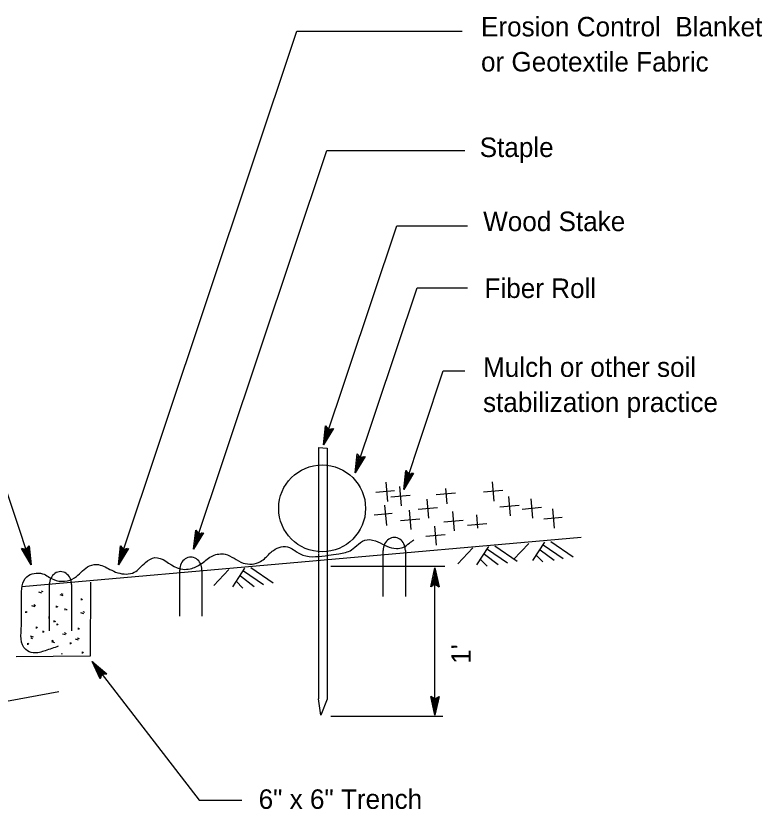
# Model space of a CAD drawing. Extents: x 6708945 to 6710368, y 1871409 to 1872338.
# Drawn here: x 6709230.9 to 6709460.4, y 1871973 to 1872217 of the extents above; entities that cross this region are included whole.
import ezdxf

# ---------------------------------------------------------------- set-up
doc = ezdxf.new("R2010")
doc.units = 0
for name, color, linetype in [('1 Control', 7, 'Continuous'), ('26 undefined', 7, 'Continuous'), ('57 Undefined', 7, 'Continuous'), ('60 Nongeo Data', 7, 'Continuous')]:
    doc.layers.add(name, color=color, linetype=linetype)

msp = doc.modelspace()

# ---------------------------------------------------------------- linework, layer by layer
at = {"layer": '1 Control'}
for p, q in [((6709343.86, 1872038.34), (6709343.86, 1872052.55)), ((6709350.7, 1872052.55), (6709350.7, 1872038.34)), ((6709281.29, 1872032.34), (6709281.29, 1872046.54)), ((6709288.12, 1872046.54), (6709288.12, 1872032.34)), ((6709241.22, 1872027.84), (6709241.22, 1872042.04)), ((6709248.06, 1872042.04), (6709248.06, 1872027.84))]:
    msp.add_line(p, q, dxfattribs=at)
for centre in [(6709347.28, 1872052.55), (6709284.7, 1872046.54), (6709244.64, 1872042.04)]:
    msp.add_ellipse(centre, major_axis=(0, 3.99), ratio=0.857645, start_param=4.712389, end_param=7.853982, dxfattribs=at)
at = {"layer": '26 undefined'}
for p, q in [((6709323.95, 1872084.22), (6709326.67, 1872084.01)), ((6709323.96, 1872084.2), (6709323.96, 1872078.02)), ((6709326.67, 1872084.01), (6709326.67, 1872078.12)), ((6709323.96, 1872078), (6709323.95, 1872051.85)), ((6709326.67, 1872078.09), (6709326.66, 1872051.6)), ((6709345.34, 1872067.65), (6709344.82, 1872073.54)), ((6709349.49, 1872066.27), (6709348.97, 1872072.21)), ((6709378, 1872067.73), (6709377.48, 1872073.67)), ((6709347.31, 1872070.84), (6709341.63, 1872070.33)), ((6709352.11, 1872069.5), (6709346.17, 1872068.97)), ((6709366.14, 1872070.17), (6709360.2, 1872069.64)), ((6709363.52, 1872066.94), (6709363.11, 1872071.63)), ((6709380.62, 1872070.96), (6709374.68, 1872070.43)), ((6709357.91, 1872062.44), (6709357.39, 1872068.37)), ((6709383.04, 1872063.2), (6709382.52, 1872069.14)), ((6709389.89, 1872062.51), (6709389.37, 1872068.44)), ((6709344.95, 1872060.25), (6709344.4, 1872066.49)), ((6709352.49, 1872058.99), (6709351.97, 1872064.92)), ((6709360.53, 1872065.66), (6709354.59, 1872065.14)), ((6709365.8, 1872058.56), (6709365.27, 1872064.49)), ((6709385.66, 1872066.43), (6709379.72, 1872065.9)), ((6709392.51, 1872065.73), (6709386.57, 1872065.2)), ((6709396.57, 1872059.44), (6709396.05, 1872065.37)), ((6709346.66, 1872063.87), (6709341.12, 1872063.38)), ((6709355.11, 1872062.21), (6709349.18, 1872061.69)), ((6709372.98, 1872059.36), (6709372.61, 1872063.49)), ((6709398.93, 1872062.64), (6709393.25, 1872062.14)), ((6709360.28, 1872054.14), (6709359.76, 1872060.07)), ((6709368.41, 1872061.78), (6709362.48, 1872061.26)), ((6709375.75, 1872060.78), (6709369.82, 1872060.26)), ((6709362.9, 1872057.36), (6709356.97, 1872056.84)), ((6709323.95, 1872051.63), (6709323.93, 1872006.88)), ((6709326.66, 1872051.67), (6709326.64, 1872006.83)), ((6709238.67, 1872040.16), (6709239.24, 1872039.88)), ((6709238.89, 1872039.43), (6709237.96, 1872039.7)), ((6709245.46, 1872038.63), (6709244.53, 1872038.9)), ((6709244.79, 1872039.36), (6709245.36, 1872039.09)), ((6709251.06, 1872037.25), (6709251.07, 1872037.73)), ((6709251.1, 1872037.7), (6709251.4, 1872037.5)), ((6709236.79, 1872035.21), (6709235.86, 1872035.48)), ((6709236.42, 1872035.94), (6709236.98, 1872035.66)), ((6709243.41, 1872035.01), (6709243.43, 1872035.5)), ((6709243.45, 1872035.46), (6709243.76, 1872035.26)), ((6709233.99, 1872033.33), (6709234.01, 1872033.81)), ((6709234.03, 1872033.78), (6709234.34, 1872033.58)), ((6709246.02, 1872034.21), (6709246.03, 1872034.7)), ((6709246.36, 1872034.51), (6709246.66, 1872034.31)), ((6709251.84, 1872033.08), (6709250.9, 1872033.35)), ((6709251.46, 1872033.81), (6709252.03, 1872033.54)), ((6709241.09, 1872032.21), (6709240.99, 1872031.62)), ((6709242.69, 1872030.48), (6709242.71, 1872030.97)), ((6709242.73, 1872030.93), (6709243.04, 1872030.73)), ((6709253.82, 1872030.44), (6709253.84, 1872030.92)), ((6709237.21, 1872028.57), (6709237.23, 1872029.05)), ((6709237.25, 1872029.02), (6709237.56, 1872028.82)), ((6709243.6, 1872029.54), (6709243.62, 1872030.03)), ((6709243.64, 1872029.99), (6709243.95, 1872029.79)), ((6709250.16, 1872028.24), (6709250.17, 1872028.72)), ((6709250.2, 1872028.69), (6709250.5, 1872028.49)), ((6709236.31, 1872025.9), (6709235.38, 1872026.17)), ((6709235.49, 1872025.73), (6709236.06, 1872025.45)), ((6709239.27, 1872027.31), (6709239.28, 1872027.8)), ((6709239.31, 1872027.76), (6709239.61, 1872027.56)), ((6709246.16, 1872026.55), (6709245.22, 1872026.82)), ((6709245.78, 1872027.28), (6709246.35, 1872027.01)), ((6709249.78, 1872025.72), (6709250.35, 1872025.45)), ((6709234.56, 1872023.55), (6709234.58, 1872024.03)), ((6709234.6, 1872024), (6709234.9, 1872023.8)), ((6709241.94, 1872024.92), (6709242.51, 1872024.65)), ((6709242.91, 1872024.19), (6709241.98, 1872024.46)), ((6709247.72, 1872023.71), (6709247.73, 1872024.2)), ((6709247.76, 1872024.16), (6709248.06, 1872023.96)), ((6709250.15, 1872024.99), (6709249.22, 1872025.26)), ((6709244.85, 1872020.91), (6709245.16, 1872020.71)), ((6709251.37, 1872020.88), (6709251.39, 1872021.36)), ((6709251.42, 1872021.33), (6709251.72, 1872021.13)), ((6709324.66, 1872001.89), (6709323.92, 1872006.88)), ((6709326.63, 1872006.83), (6709324.66, 1872001.89))]:
    msp.add_line(p, q, dxfattribs=at)
for points in [[(6709404.75, 1872056.52), (6709232.71, 1872041.38)], [(6709253.81, 1872042.84), (6709253.76, 1872020.04), (6709231, 1872019.87)]]:
    msp.add_lwpolyline(points, dxfattribs=at)
at = {"layer": '57 Undefined'}
for p, q in [((6709262.46, 1872048.14), (6709317.29, 1872212.24)), ((6709317.29, 1872212.24), (6709368.15, 1872212.24)), ((6709235.65, 1872048.14), (6709181.55, 1872210.09)), ((6709285.58, 1872052.93), (6709326.55, 1872175.56)), ((6709326.55, 1872175.56), (6709368.95, 1872175.56)), ((6709325.5, 1872085.01), (6709348.02, 1872152.43)), ((6709348.02, 1872152.43), (6709369.74, 1872152.43)), ((6709335.27, 1872076.4), (6709354.28, 1872133.29)), ((6709354.28, 1872133.29), (6709369.74, 1872133.29)), ((6709350.17, 1872071.31), (6709362.35, 1872107.76)), ((6709362.35, 1872107.76), (6709368.95, 1872107.76)), ((6709362.77, 1872047.64), (6709327.76, 1872047.64)), ((6709359.79, 1872001.89), (6709359.79, 1872047.17)), ((6709254.34, 1872018.43), (6709287.24, 1871975.73)), ((6709201.53, 1872001.18), (6709244.07, 1872009.21)), ((6709362.24, 1872001.44), (6709327.76, 1872001.44)), ((6709287.24, 1871975.73), (6709300.37, 1871975.73))]:
    msp.add_line(p, q, dxfattribs=at)
at = {"layer": '60 Nongeo Data'}
for p, q in [((6709326.11, 1872090.88), (6709326.11, 1872090.88)), ((6709328.54, 1872090.06), (6709328.54, 1872090.06)), ((6709325.5, 1872085.01), (6709325.5, 1872085.01)), ((6709335.89, 1872082.27), (6709335.89, 1872082.27)), ((6709338.32, 1872081.46), (6709338.32, 1872081.46)), ((6709350.79, 1872077.18), (6709350.79, 1872077.18)), ((6709335.27, 1872076.4), (6709335.27, 1872076.4)), ((6709353.22, 1872076.37), (6709353.22, 1872076.37)), ((6709350.17, 1872071.31), (6709350.17, 1872071.31)), ((6709286.2, 1872058.8), (6709286.2, 1872058.8)), ((6709288.63, 1872057.98), (6709288.63, 1872057.98)), ((6709388.63, 1872054.73), (6709383.97, 1872049.77)), ((6709393.43, 1872055.14), (6709389.74, 1872049.44)), ((6709395.38, 1872055.29), (6709402.27, 1872050.6)), ((6709232.61, 1872053.2), (6709232.61, 1872053.2)), ((6709235.04, 1872054.01), (6709235.04, 1872054.01)), ((6709263.08, 1872054.01), (6709263.08, 1872054.01)), ((6709265.51, 1872053.2), (6709265.51, 1872053.2)), ((6709285.58, 1872052.93), (6709285.58, 1872052.93)), ((6709371.47, 1872053.41), (6709366.81, 1872048.44)), ((6709376.28, 1872053.81), (6709372.58, 1872048.12)), ((6709375.94, 1872052.97), (6709382.09, 1872048.78)), ((6709378.23, 1872053.97), (6709385.11, 1872049.27)), ((6709392.18, 1872052.74), (6709396.41, 1872049.54)), ((6709393.09, 1872054.3), (6709399.25, 1872050.11)), ((6709375.03, 1872051.41), (6709379.26, 1872048.21)), ((6709390.93, 1872051.09), (6709392.97, 1872049.01)), ((6709235.65, 1872048.14), (6709235.65, 1872048.14)), ((6709262.46, 1872048.14), (6709262.46, 1872048.14)), ((6709373.78, 1872049.76), (6709375.81, 1872047.68)), ((6709296.4, 1872046.7), (6709291.74, 1872041.74)), ((6709301.2, 1872047.11), (6709297.51, 1872041.41)), ((6709300.86, 1872046.27), (6709307.02, 1872042.08)), ((6709303.15, 1872047.26), (6709310.04, 1872042.57)), ((6709359.79, 1872047.17), (6709359.79, 1872047.17)), ((6709298.7, 1872043.06), (6709300.74, 1872040.98)), ((6709299.95, 1872044.71), (6709304.18, 1872041.51)), ((6709358.51, 1872041.41), (6709358.51, 1872041.41)), ((6709361.07, 1872041.41), (6709361.07, 1872041.41)), ((6709254.34, 1872018.43), (6709254.34, 1872018.43)), ((6709258.87, 1872014.65), (6709258.87, 1872014.65)), ((6709256.84, 1872013.08), (6709256.84, 1872013.08)), ((6709358.52, 1872007.65), (6709358.52, 1872007.65)), ((6709361.08, 1872007.65), (6709361.08, 1872007.65)), ((6709359.79, 1872001.89), (6709359.79, 1872001.89))]:
    msp.add_line(p, q, dxfattribs=at)
for points in [[(6709328.54, 1872090.06), (6709325.5, 1872085.01), (6709326.11, 1872090.88), (6709326.37, 1872090.57), (6709325.92, 1872086.28), (6709328.15, 1872089.98), (6709327.77, 1872089.89), (6709326.34, 1872087.52), (6709326.63, 1872090.27), (6709326.88, 1872089.97), (6709326.76, 1872088.78), (6709327.38, 1872089.81), (6709327.08, 1872089.74), (6709326.11, 1872090.88), (6709327.08, 1872089.74)], [(6709338.32, 1872081.46), (6709335.27, 1872076.4), (6709335.89, 1872082.27), (6709336.15, 1872081.97), (6709335.69, 1872077.67), (6709337.93, 1872081.37), (6709337.54, 1872081.29), (6709336.12, 1872078.92), (6709336.4, 1872081.67), (6709336.66, 1872081.37), (6709336.54, 1872080.18), (6709337.16, 1872081.2), (6709336.86, 1872081.14), (6709335.89, 1872082.27), (6709336.86, 1872081.14)], [(6709353.22, 1872076.37), (6709350.17, 1872071.31), (6709350.79, 1872077.18), (6709351.05, 1872076.88), (6709350.59, 1872072.58), (6709352.83, 1872076.28), (6709352.45, 1872076.2), (6709351.02, 1872073.83), (6709351.3, 1872076.58), (6709351.56, 1872076.27), (6709351.44, 1872075.09), (6709352.06, 1872076.11), (6709351.76, 1872076.05), (6709350.79, 1872077.18), (6709351.76, 1872076.05)], [(6709288.63, 1872057.98), (6709285.58, 1872052.93), (6709286.2, 1872058.8), (6709286.45, 1872058.5), (6709286, 1872054.2), (6709288.24, 1872057.9), (6709287.85, 1872057.82), (6709286.42, 1872055.44), (6709286.71, 1872058.19), (6709286.97, 1872057.89), (6709286.85, 1872056.7), (6709287.46, 1872057.73), (6709287.16, 1872057.66), (6709286.2, 1872058.8), (6709287.16, 1872057.66)], [(6709235.04, 1872054.01), (6709235.65, 1872048.14), (6709232.61, 1872053.2), (6709233, 1872053.12), (6709235.22, 1872049.41), (6709234.79, 1872053.71), (6709234.53, 1872053.41), (6709234.81, 1872050.66), (6709233.39, 1872053.03), (6709233.78, 1872052.94), (6709234.39, 1872051.92), (6709234.27, 1872053.11), (6709234.07, 1872052.88), (6709232.61, 1872053.2), (6709234.07, 1872052.88)], [(6709265.51, 1872053.2), (6709262.46, 1872048.14), (6709263.08, 1872054.01), (6709263.33, 1872053.71), (6709262.88, 1872049.41), (6709265.12, 1872053.11), (6709264.73, 1872053.03), (6709263.31, 1872050.66), (6709263.59, 1872053.41), (6709263.85, 1872053.11), (6709263.73, 1872051.92), (6709264.35, 1872052.94), (6709264.04, 1872052.88), (6709263.08, 1872054.01), (6709264.04, 1872052.88)], [(6709358.51, 1872041.41), (6709359.79, 1872047.17), (6709361.07, 1872041.41), (6709360.73, 1872041.62), (6709359.8, 1872045.84), (6709358.85, 1872041.61), (6709359.19, 1872041.82), (6709359.79, 1872044.52), (6709360.39, 1872041.82), (6709360.05, 1872042.03), (6709359.79, 1872043.19), (6709359.53, 1872042.02), (6709359.79, 1872042.18), (6709361.07, 1872041.41), (6709359.79, 1872042.18)], [(6709256.84, 1872013.08), (6709254.34, 1872018.43), (6709258.87, 1872014.65), (6709258.48, 1872014.6), (6709255.16, 1872017.38), (6709256.99, 1872013.45), (6709257.13, 1872013.82), (6709255.96, 1872016.33), (6709258.08, 1872014.56), (6709257.69, 1872014.51), (6709256.77, 1872015.28), (6709257.28, 1872014.19), (6709257.39, 1872014.48), (6709258.87, 1872014.65), (6709257.39, 1872014.48)], [(6709361.08, 1872007.65), (6709359.79, 1872001.89), (6709358.52, 1872007.65), (6709358.86, 1872007.45), (6709359.79, 1872003.23), (6709360.74, 1872007.45), (6709360.4, 1872007.25), (6709359.79, 1872004.54), (6709359.2, 1872007.24), (6709359.54, 1872007.04), (6709359.8, 1872005.87), (6709360.06, 1872007.04), (6709359.79, 1872006.88), (6709358.52, 1872007.65), (6709359.79, 1872006.88)]]:
    msp.add_lwpolyline(points, close=True, dxfattribs=at)
msp.add_circle((6709325.08, 1872065.5), 13.36, dxfattribs=at)
msp.add_spline([(6709243.96, 1872023.07), (6709239.95, 1872021.73), (6709236.27, 1872021.06), (6709233.93, 1872022.06), (6709232.59, 1872029.42), (6709232.59, 1872038.12), (6709234.27, 1872044.48), (6709239.1, 1872045.39), (6709242.55, 1872043.59), (6709248.98, 1872044.14), (6709252.91, 1872047.49), (6709255.76, 1872048.24), (6709259.81, 1872046.74), (6709262.21, 1872045.69), (6709267.31, 1872045.84), (6709270.76, 1872048.84), (6709273.61, 1872050.34), (6709280.52, 1872047.19), (6709285.02, 1872047.04), (6709288.17, 1872048.69), (6709291.47, 1872050.94), (6709295.22, 1872051.39), (6709300.77, 1872048.69), (6709306.15, 1872049.16), (6709307.68, 1872050.34), (6709310.08, 1872052.59), (6709315.01, 1872053.51), (6709316.64, 1872052.5), (6709319.19, 1872051.12), (6709327.03, 1872051.09), (6709330.19, 1872051.54), (6709334.11, 1872052.71), (6709336.25, 1872054.51), (6709338.92, 1872055.85), (6709342.26, 1872055.18), (6709344.94, 1872053.84), (6709347.95, 1872053.17), (6709349.95, 1872053.51), (6709351.96, 1872054.84), (6709353.3, 1872055.85)], degree=3, dxfattribs=at)

# ---------------------------------------------------------------- texts
at = {"layer": '57 Undefined'}
for s, p in [('Erosion Control  Blanket ', (6709373.94, 1872210.66)), ('or Geotextile Fabric', (6709373.94, 1872199.86)), ('Staple', (6709373.54, 1872173.56)), ('Wood Stake', (6709374.6, 1872150.77)), ('Fiber Roll', (6709375.03, 1872130.2)), ('Mulch or other soil ', (6709374.57, 1872105.94)), ('stabilization practice', (6709374.57, 1872095.14)), ('6" x 6" Trench ', (6709305.56, 1871973.07))]:
    msp.add_text(s, height=6, dxfattribs=at).set_placement(p)
msp.add_text("1'", height=6, rotation=90, dxfattribs=at).set_placement((6709370.81, 1872017.7))

doc.saveas('drawing.dxf')
